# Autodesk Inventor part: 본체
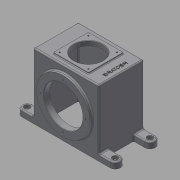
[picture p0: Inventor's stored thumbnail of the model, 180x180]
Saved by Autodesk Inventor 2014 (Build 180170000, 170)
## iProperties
Created: 2016-11
Part Number: 본체
Material: 일반
Document SubType Name: Modeling
Designer: mduedu
Density: 1 g/cm^3
Appearance: 기본값
Mass: 790.871 g
Surface Area: 1967.93 cm^2
Volume: 790.871 cm^3
Author: mduedu
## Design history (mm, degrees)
sketch "스케치1"
  geometry: L1 (-80, 0)-(80, 0); L2 (80, 0)-(80, 160); L3 (80, 160)-(-80, 160); L4 (-80, 160)-(-80, 0); 2 further points
  constraints: 8 end point, 2 parallel, 1 coincident, 1 horizontal, 1 midpoint, 1 perpendicular
  dimensions: "d0" = 160 distance of L2.end L3.end; "d2" = 160 distance of L1.end L2.end
extrude "돌출1" new body sketch "스케치1" stored distance "d3" = 110; taper "d4" = 0 deg
sketch "스케치2"
  geometry: L1 (-80, -55)-(-80, 55) reference; L2 (-80, -55)-(-120, -55); L3 (-120, -55)-(-120, 55); L4 (-120, 55)-(-80, 55); L5 (-80, 55)-(-80, -55); 1 further point
  constraints: 8 end point, 2 parallel, 1 horizontal, 1 perpendicular
  dimensions: "d5" = 40 distance of L1.end L3.end
extrude "돌출2" join sketch "스케치2" distance "d6" = 15; taper "d7" = 0 deg
sketch "스케치3"
  geometry: L1 (80, 55)-(80, -55) reference; L2 (120, -55)-(120, 55) reference; L3 (80, 30)-(120, 30); L4 (120, 30)-(120, -30); L5 (120, -30)-(80, -30); L6 (80, -30)-(80, 30); L7 (-80, -55)-(120, -55) reference; L8 (-80, 55)-(120, 55) reference; 1 further point
  constraints: 8 end point, 2 parallel, 2 point on line, 1 horizontal, 1 perpendicular
  dimensions: "d8" = 25 distance between parallel lines of L5 L7; "d9" = 25 distance between parallel lines of L3 L8 (= d8)
extrude "돌출3" cut sketch "스케치3" stored distance "d10" = 15; taper "d11" = 0 deg
fillet "모깎기1"
fillet "모깎기2"
hole "구멍1" diameter "d14" = 9; stored, may be unused: countersink angle "d18" = 90 deg, drill point angle "d20" = 118 deg; dims "d12" = 10, "d13" = 10, "d15" = 6, "d16" = 14, "d17" = 8, "d19" = 8
fillet "모깎기3" dims "d21" = 3
fillet "모깎기4" dims "d22" = 3
sketch "스케치4"
  geometry: L1 (80, 160)-(-80, 160) reference; L2 (-80, 17.196)-(-80, 160) reference; L3 (80, 17.196)-(80, 160) reference; L4 (-72, 0)-(-72, 152); L5 (-72, 152)-(72, 152); L6 (72, 152)-(72, 0); L7 (-72, 0)-(72, 0); 2 further points
  constraints: 8 end point, 1 coincident, 1 midpoint, 1 perpendicular
  dimensions: "d23" = 8 distance between parallel lines of L5 L1; "d24" = 8 distance between parallel lines of L3 L6 (= d23); "d25" = 8 distance between parallel lines of L2 L4 (= d23)
extrude "돌출4" cut sketch "스케치4" stored distance "d26" = 94; taper "d27" = 0 deg
fillet "모깎기5" dims "d28" = 3
fillet "모깎기6" dims "d29" = 3
fillet "모깎기7" dims "d30" = 3
fillet "모깎기8" dims "d31" = 3
sketch "스케치5"
  geometry: C1 r 65 at (0, 80); 1 further point
  constraints: 1 centre point, 1 vertical alignment
  dimensions: "d32" = 130 diameter of C1; "d33" = 80 distance of C1.centre point (0, 0)
extrude "돌출5" join sketch "스케치5" distance "d34" = 7; taper "d35" = 0 deg
sketch "스케치6"
  geometry: C1 r 35 at (77, 51.5); 2 further points
  constraints: 1 centre point, 1 coincident, 1 vertical alignment
  dimensions: "d36" = 70 diameter of C1; "d77" = 0.5 distance of point (77, 52) point (77, 51.5)
extrude "돌출6" cut sketch "스케치6" stored distance "d37" = 7; taper "d38" = 0 deg
sketch "스케치7"
  geometry: L1 (34.5, 9)-(119.5, 9); L2 (119.5, 9)-(119.5, 94); L3 (119.5, 94)-(34.5, 94); L4 (34.5, 94)-(34.5, 9); L5 (34.5, 9)-(119.5, 94); L6 (119.5, 9)-(34.5, 94); C1 r 35 at (77, 51.5) reference; 2 further points
  constraints: 12 end point, 3 midpoint, 2 parallel, 1 coincident, 1 horizontal, 1 perpendicular
  dimensions: "d39" = 85 distance of L3.end L2.end; "d40" = 85 distance of L1.end L2.end (= d39)
extrude "돌출7" join sketch "스케치7" distance "d41" = 3; taper "d42" = 0 deg
fillet "모깎기9" dims "d43" = 3
fillet "모깎기10" dims "d44" = 2
hole "구멍2" diameter "d47" = 95; stored, may be unused: countersink angle "d51" = 90 deg, drill point angle "d53" = 118 deg; dims "d45" = 10, "d46" = 10, "d48" = 6, "d49" = 14, "d50" = 8, "d52" = 8
chamfer "모따기1" distance "d54" = 1; stored, may be unused: second distance "d55" = 2, angle "d56" = 45 deg
sketch "스케치8"
  geometry: C1 r 65 at (0, 80) reference; C2 r 31.5 at (0, 80); 1 further point
  constraints: 1 centre point, 1 coincident
  dimensions: "d57" = 63 diameter of C2
extrude "돌출8" join sketch "스케치8" distance "d58" = 14; taper "d59" = 0 deg
hole "구멍3" diameter "d62" = 30; stored, may be unused: countersink angle "d66" = 90 deg, drill point angle "d68" = 0 deg; dims "d60" = 10, "d61" = 10, "d63" = 6, "d64" = 47, "d65" = 14, "d67" = 17
fillet "모깎기11" dims "d69" = 3
fillet "모깎기12" dims "d70" = 3
fillet "모깎기13" dims "d71" = 0.5
chamfer "모따기2" distance "d72" = 1; stored, may be unused: second distance "d73" = 2, angle "d74" = 45 deg
fillet "모깎기14" dims "d75" = 3
sketch "스케치9"
  geometry: L1 (157, 0)-(157, 104) reference; L2 (77, 52)-(157, 52); 1 further point
  constraints: 2 end point, 1 midpoint, 1 point on line, 1 other
  dimensions: "d78" = 65 distance of point (142, 52) L2.start
feature "엠보싱1" sketch "스케치9" dims "d79" = 0.5, "d80" = 0
sketch "스케치10"
  geometry: 4 further points
  constraints: 4 other
hole "구멍4" sketch "스케치10" at (0, -55), (55, 0), (-55, 0), (0, 55) diameter "d81" = 3.242; stored, may be unused: countersink angle "d85" = 90 deg, drill point angle "d87" = 120 deg; dims "d82" = 6.6, "d83" = 4, "d84" = 2, "d86" = 8.6
sketch "스케치11"
  geometry: 4 further points
  constraints: 4 other
hole "구멍5" sketch "스케치11" at (42, 86.5), (112, 86.5), (112, 16.5), (42, 16.5) diameter "d88" = 3.242; stored, may be unused: countersink angle "d92" = 90 deg, drill point angle "d94" = 120 deg; dims "d89" = 6.6, "d90" = 4, "d91" = 2, "d93" = 8.6
node "솔리드1"
mirror "대칭1"
mirror "대칭2"
mirror "대칭3"
